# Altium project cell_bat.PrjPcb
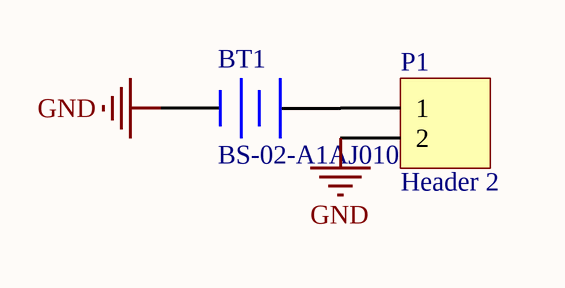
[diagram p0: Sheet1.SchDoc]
1 sheet, 2 parts. Net scope: global (net labels, ports and power ports of the same name join across sheets).
Board file: PCB1.PcbDoc

## Sheet Sheet1.SchDoc
size A2; SheetNumber: 1; SheetTotal: 1

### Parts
BT1  BS-02-A1AJ010  [BS-02-A1AJ010]
P1  Header 2  [2x2.0mm_smt]

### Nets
GND: BT1.2(-) P1.2
NetBT1_1: BT1.1(+) P1.1

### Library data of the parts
BT1 = Battery: Multicell Battery
P1 = Header 2: Header, 2-Pin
